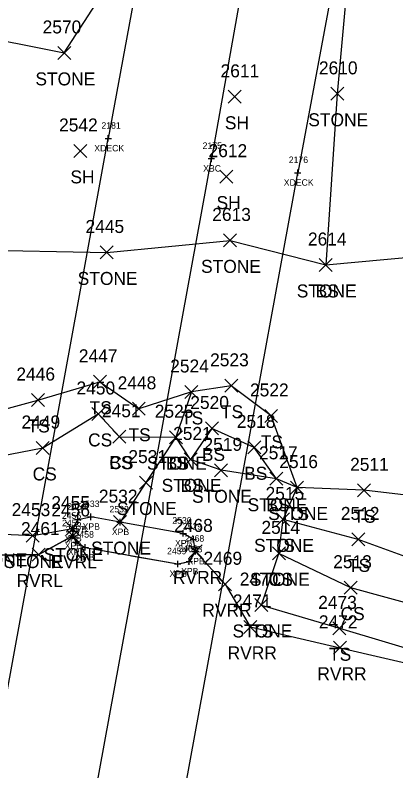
# Model space of a CAD drawing. Extents: x 1472022 to 1479249, y 777216 to 786527.
# Drawn here: x 1473693.9 to 1473752.5, y 779650.8 to 779767.2 of the extents above; entities that cross this region are included whole.
import ezdxf

# ---------------------------------------------------------------- set-up
doc = ezdxf.new("R2010")
doc.units = 0
for name, color, linetype in [('B_A', 7, 'Continuous'), ('B_I', 7, 'Continuous'), ('B_TIC', 7, 'Continuous'), ('BELB', 7, 'Continuous'), ('BSUBM', 7, 'Continuous'), ('L_A', 7, 'Continuous'), ('L_I', 7, 'Continuous'), ('L_TIC', 7, 'Continuous'), ('LASF', 7, 'Continuous'), ('LAWE', 7, 'Continuous'), ('LELB', 7, 'Continuous'), ('LSOGP', 7, 'Continuous')]:
    doc.layers.add(name, color=color, linetype=linetype)

msp = doc.modelspace()

# ---------------------------------------------------------------- linework, layer by layer
at = {"layer": 'B_TIC'}
for p, q in [((1473708.22, 779748.21), (1473708.3, 779748.21)), ((1473708.22, 779748.21), (1473708.3, 779748.21)), ((1473724.09, 779745.09), (1473724.17, 779745.09)), ((1473724.09, 779745.09), (1473724.17, 779745.09)), ((1473737.38, 779742.92), (1473737.46, 779742.92)), ((1473737.38, 779742.92), (1473737.46, 779742.92)), ((1473703.55, 779689.5), (1473703.62, 779689.5)), ((1473703.55, 779689.5), (1473703.62, 779689.5)), ((1473705.53, 779689.92), (1473705.6, 779689.92)), ((1473705.53, 779689.92), (1473705.6, 779689.92)), ((1473702.72, 779688.1), (1473702.79, 779688.1)), ((1473710.03, 779689.1), (1473710.1, 779689.1)), ((1473702.76, 779686.97), (1473702.84, 779686.97)), ((1473719.75, 779687.36), (1473719.82, 779687.36)), ((1473703.28, 779686.01), (1473703.36, 779686.01)), ((1473721.32, 779686.44), (1473721.39, 779686.44)), ((1473704.67, 779685.21), (1473704.74, 779685.21)), ((1473721.66, 779684.59), (1473721.74, 779684.59)), ((1473718.91, 779682.65), (1473718.98, 779682.65)), ((1473720.69, 779683.03), (1473720.76, 779683.03))]:
    msp.add_line(p, q, dxfattribs=at)
for points in [[(1473708.22, 779747.71), (1473708.22, 779748.71)], [(1473708.22, 779747.71), (1473708.22, 779748.71)], [(1473707.72, 779748.21), (1473708.72, 779748.21)], [(1473707.72, 779748.21), (1473708.72, 779748.21)], [(1473723.59, 779745.09), (1473724.59, 779745.09)], [(1473723.59, 779745.09), (1473724.59, 779745.09)], [(1473724.09, 779744.59), (1473724.09, 779745.59)], [(1473724.09, 779744.59), (1473724.09, 779745.59)], [(1473736.88, 779742.92), (1473737.88, 779742.92)], [(1473736.88, 779742.92), (1473737.88, 779742.92)], [(1473737.38, 779742.42), (1473737.38, 779743.42)], [(1473737.38, 779742.42), (1473737.38, 779743.42)], [(1473705.52, 779689.42), (1473705.52, 779690.42)], [(1473705.52, 779689.42), (1473705.52, 779690.42)], [(1473703.04, 779689.5), (1473704.04, 779689.5)], [(1473703.04, 779689.5), (1473704.04, 779689.5)], [(1473703.54, 779689), (1473703.54, 779690)], [(1473703.54, 779689), (1473703.54, 779690)], [(1473705.02, 779689.92), (1473706.02, 779689.92)], [(1473705.02, 779689.92), (1473706.02, 779689.92)], [(1473710.03, 779688.6), (1473710.03, 779689.6)], [(1473702.21, 779688.1), (1473703.21, 779688.1)], [(1473702.71, 779687.6), (1473702.71, 779688.6)], [(1473709.53, 779689.1), (1473710.53, 779689.1)], [(1473702.26, 779686.97), (1473703.26, 779686.97)], [(1473702.76, 779686.47), (1473702.76, 779687.47)], [(1473719.25, 779687.36), (1473720.25, 779687.36)], [(1473719.75, 779686.86), (1473719.75, 779687.86)], [(1473721.31, 779685.94), (1473721.31, 779686.94)], [(1473702.78, 779686.01), (1473703.78, 779686.01)], [(1473703.28, 779685.51), (1473703.28, 779686.51)], [(1473704.66, 779684.71), (1473704.66, 779685.71)], [(1473720.81, 779686.44), (1473721.81, 779686.44)], [(1473704.16, 779685.21), (1473705.16, 779685.21)], [(1473721.16, 779684.59), (1473722.16, 779684.59)], [(1473721.66, 779684.09), (1473721.66, 779685.09)], [(1473720.69, 779682.53), (1473720.69, 779683.53)], [(1473718.4, 779682.65), (1473719.4, 779682.65)], [(1473718.9, 779682.15), (1473718.9, 779683.15)], [(1473720.19, 779683.03), (1473721.19, 779683.03)]]:
    msp.add_lwpolyline(points, dxfattribs=at)
at = {"layer": 'BELB'}
for points in [[(1473719.43, 779809.21), (1473708.22, 779748.21)], [(1473735, 779806.45), (1473724.09, 779745.09)], [(1473748.73, 779803.86), (1473737.38, 779742.92)], [(1473632.64, 779331.64), (1473643.77, 779393.67), (1473661.77, 779492.35), (1473674.97, 779565.3), (1473690.2, 779649.78), (1473708.22, 779748.21)], [(1473648.23, 779328.95), (1473658.53, 779391.7), (1473677.73, 779489.35), (1473690.33, 779561.53), (1473706.17, 779646.87), (1473724.09, 779745.09)], [(1473662.07, 779326.37), (1473673.18, 779388.74), (1473691.04, 779487.09), (1473704.3, 779559.92), (1473719.46, 779644.73), (1473737.38, 779742.92)]]:
    msp.add_lwpolyline(points, dxfattribs=at)
at = {"layer": 'BSUBM'}
for points in [[(1473703.54, 779689.5), (1473702.71, 779688.1), (1473702.76, 779686.97), (1473703.28, 779686.01), (1473704.66, 779685.21), (1473718.9, 779682.65), (1473720.69, 779683.03), (1473721.66, 779684.59), (1473721.31, 779686.44), (1473719.75, 779687.36), (1473710.03, 779689.1), (1473705.52, 779689.92)], [(1473703.54, 779689.5), (1473705.52, 779689.92)]]:
    msp.add_lwpolyline(points, dxfattribs=at)
at = {"layer": 'L_TIC'}
for points in [[(1473700.45, 779760.38), (1473702.45, 779762.38)], [(1473702.45, 779760.38), (1473700.45, 779762.38)], [(1473726.67, 779753.62), (1473728.67, 779755.62)], [(1473728.67, 779753.62), (1473726.67, 779755.62)], [(1473742.47, 779754.08), (1473744.47, 779756.08)], [(1473744.47, 779754.08), (1473742.47, 779756.08)], [(1473702.9, 779745.28), (1473704.9, 779747.28)], [(1473704.9, 779745.28), (1473702.9, 779747.28)], [(1473725.39, 779741.32), (1473727.39, 779743.32)], [(1473727.39, 779741.32), (1473725.39, 779743.32)], [(1473725.96, 779731.5), (1473727.96, 779733.5)], [(1473727.96, 779731.5), (1473725.96, 779733.5)], [(1473706.97, 779729.64), (1473708.97, 779731.64)], [(1473708.97, 779729.64), (1473706.97, 779731.64)], [(1473740.69, 779727.71), (1473742.69, 779729.71)], [(1473742.69, 779727.71), (1473740.69, 779729.71)], [(1473740.69, 779727.71), (1473742.69, 779729.71)], [(1473742.69, 779727.71), (1473740.69, 779729.71)], [(1473740.69, 779727.71), (1473742.69, 779729.71)], [(1473742.69, 779727.71), (1473740.69, 779729.71)], [(1473705.94, 779709.72), (1473707.94, 779711.72)], [(1473707.94, 779709.72), (1473705.94, 779711.72)], [(1473720.01, 779708.15), (1473722.01, 779710.15)], [(1473722.01, 779708.15), (1473720.01, 779710.15)], [(1473726.15, 779709.1), (1473728.15, 779711.1)], [(1473728.15, 779709.1), (1473726.15, 779711.1)], [(1473696.38, 779706.91), (1473698.38, 779708.91)], [(1473698.38, 779706.91), (1473696.38, 779708.91)], [(1473705.67, 779704.76), (1473707.67, 779706.76)], [(1473707.67, 779704.76), (1473705.67, 779706.76)], [(1473711.92, 779705.56), (1473713.92, 779707.56)], [(1473713.92, 779705.56), (1473711.92, 779707.56)], [(1473732.29, 779704.46), (1473734.29, 779706.46)], [(1473734.29, 779704.46), (1473732.29, 779706.46)], [(1473723.18, 779702.53), (1473725.18, 779704.53)], [(1473725.18, 779702.53), (1473723.18, 779704.53)], [(1473708.93, 779701.26), (1473710.93, 779703.26)], [(1473710.93, 779701.26), (1473708.93, 779703.26)], [(1473708.93, 779701.26), (1473710.93, 779703.26)], [(1473710.93, 779701.26), (1473708.93, 779703.26)], [(1473717.63, 779701.18), (1473719.63, 779703.18)], [(1473719.63, 779701.18), (1473717.63, 779703.18)], [(1473717.63, 779701.18), (1473719.63, 779703.18)], [(1473719.63, 779701.18), (1473717.63, 779703.18)], [(1473717.63, 779701.18), (1473719.63, 779703.18)], [(1473719.63, 779701.18), (1473717.63, 779703.18)], [(1473697.13, 779699.52), (1473699.13, 779701.52)], [(1473699.13, 779699.52), (1473697.13, 779701.52)], [(1473729.69, 779699.62), (1473731.69, 779701.62)], [(1473731.69, 779699.62), (1473729.69, 779701.62)], [(1473719.89, 779697.76), (1473721.89, 779699.76)], [(1473721.89, 779697.76), (1473719.89, 779699.76)], [(1473719.89, 779697.76), (1473721.89, 779699.76)], [(1473721.89, 779697.76), (1473719.89, 779699.76)], [(1473724.57, 779696.08), (1473726.57, 779698.08)], [(1473726.57, 779696.08), (1473724.57, 779698.08)], [(1473713, 779694.19), (1473715, 779696.19)], [(1473715, 779694.19), (1473713, 779696.19)], [(1473733.11, 779694.77), (1473735.11, 779696.77)], [(1473735.11, 779694.77), (1473733.11, 779696.77)], [(1473733.11, 779694.77), (1473735.11, 779696.77)], [(1473735.11, 779694.77), (1473733.11, 779696.77)], [(1473736.29, 779693.42), (1473738.29, 779695.42)], [(1473738.29, 779693.42), (1473736.29, 779695.42)], [(1473736.29, 779693.42), (1473738.29, 779695.42)], [(1473738.29, 779693.42), (1473736.29, 779695.42)], [(1473746.56, 779693), (1473748.56, 779695)], [(1473748.56, 779693), (1473746.56, 779695)], [(1473734.12, 779688.52), (1473736.12, 779690.52)], [(1473736.12, 779688.52), (1473734.12, 779690.52)], [(1473734.12, 779688.52), (1473736.12, 779690.52)], [(1473736.12, 779688.52), (1473734.12, 779690.52)], [(1473709.03, 779688.1), (1473711.03, 779690.1)], [(1473711.03, 779688.1), (1473709.03, 779690.1)], [(1473695.6, 779686.02), (1473697.6, 779688.02)], [(1473697.6, 779686.02), (1473695.6, 779688.02)], [(1473701.71, 779687.1), (1473703.71, 779689.1)], [(1473703.71, 779687.1), (1473701.71, 779689.1)], [(1473701.76, 779685.97), (1473703.76, 779687.97)], [(1473703.76, 779685.97), (1473701.76, 779687.97)], [(1473745.7, 779685.44), (1473747.7, 779687.44)], [(1473747.7, 779685.44), (1473745.7, 779687.44)], [(1473696.52, 779683.1), (1473698.52, 779685.1)], [(1473698.52, 779683.1), (1473696.52, 779685.1)], [(1473720.66, 779683.59), (1473722.66, 779685.59)], [(1473722.66, 779683.59), (1473720.66, 779685.59)], [(1473733.48, 779683.29), (1473735.48, 779685.29)], [(1473735.48, 779683.29), (1473733.48, 779685.29)], [(1473733.48, 779683.29), (1473735.48, 779685.29)], [(1473735.48, 779683.29), (1473733.48, 779685.29)], [(1473725.19, 779678.53), (1473727.19, 779680.53)], [(1473727.19, 779678.53), (1473725.19, 779680.53)], [(1473744.53, 779678), (1473746.53, 779680)], [(1473746.53, 779678), (1473744.53, 779680)], [(1473730.8, 779675.33), (1473732.8, 779677.33)], [(1473732.8, 779675.33), (1473730.8, 779677.33)], [(1473730.8, 779675.33), (1473732.8, 779677.33)], [(1473732.8, 779675.33), (1473730.8, 779677.33)], [(1473729.08, 779671.96), (1473731.08, 779673.96)], [(1473731.08, 779671.96), (1473729.08, 779673.96)], [(1473742.79, 779671.74), (1473744.79, 779673.74)], [(1473744.79, 779671.74), (1473742.79, 779673.74)], [(1473742.89, 779668.74), (1473744.89, 779670.74)], [(1473744.89, 779668.74), (1473742.89, 779670.74)]]:
    msp.add_lwpolyline(points, dxfattribs=at)
at = {"layer": 'LASF'}
for points in [[(1473645.76, 779818.01), (1473644.27, 779813.32), (1473640.68, 779797.78), (1473635.77, 779778.37), (1473629.81, 779762.77), (1473624.6, 779746.95), (1473638.08, 779739.89), (1473662.02, 779736.43), (1473680.36, 779732.63), (1473687.24, 779731.02), (1473707.97, 779730.64), (1473726.96, 779732.5), (1473741.69, 779728.71)], [(1473674.63, 779812.66), (1473674.49, 779800.35), (1473673.09, 779784.2), (1473672.47, 779768.8), (1473686.21, 779764.41), (1473701.45, 779761.38), (1473708.8, 779772.85), (1473712.08, 779786.76), (1473716.54, 779806.01), (1473719.24, 779801.78), (1473727.32, 779798.69), (1473745.52, 779794.84), (1473745.88, 779788.84), (1473745.17, 779774.32), (1473743.47, 779755.08), (1473741.69, 779728.71)], [(1473556.2, 779785.03), (1473569.27, 779768.84), (1473581.85, 779759.61), (1473593.48, 779752.19), (1473598.64, 779740.18), (1473605.84, 779732.05), (1473622.09, 779716.93), (1473631.22, 779710.18), (1473652.96, 779708.5), (1473668.38, 779700.26), (1473681.15, 779692.51), (1473691, 779687.28), (1473696.6, 779687.02), (1473702.71, 779688.1)], [(1473731.8, 779676.33), (1473734.48, 779684.29), (1473735.12, 779689.52), (1473737.29, 779694.42), (1473734.11, 779695.77), (1473725.57, 779697.08), (1473720.89, 779698.76), (1473718.63, 779702.18), (1473714, 779695.19), (1473710.03, 779689.1)]]:
    msp.add_lwpolyline(points, dxfattribs=at)
at = {"layer": 'LAWE'}
for points in [[(1473702.76, 779686.97), (1473697.52, 779684.1), (1473689.85, 779684), (1473680.09, 779685.3), (1473668.84, 779689.31), (1473659.37, 779694.87), (1473652.17, 779699.65), (1473647.05, 779700.52)], [(1473721.66, 779684.59), (1473726.19, 779679.53), (1473730.08, 779672.96), (1473743.89, 779669.74), (1473756.99, 779666.69), (1473766.52, 779665.42), (1473779.36, 779661.55), (1473796.16, 779658.44), (1473812.33, 779658.77), (1473832.71, 779656.84), (1473845.94, 779659.73)]]:
    msp.add_lwpolyline(points, dxfattribs=at)
at = {"layer": 'LELB'}
for points in [[(1473604.95, 779751.89), (1473605.35, 779747.38), (1473618.12, 779740.94), (1473634.73, 779722.55), (1473655.83, 779716.43), (1473671, 779708.65), (1473684.35, 779704.32), (1473697.38, 779707.91), (1473706.94, 779710.72), (1473712.92, 779706.56)], [(1473605.35, 779747.38), (1473615.44, 779741.31), (1473625.67, 779718.9), (1473632.86, 779714.34), (1473652.96, 779708.5), (1473655.04, 779713.83), (1473670.13, 779704.35), (1473683.24, 779697.66), (1473698.13, 779700.52), (1473706.67, 779705.76), (1473709.93, 779702.26)], [(1473741.69, 779728.71), (1473760.69, 779730.5)], [(1473731.8, 779676.33), (1473743.79, 779672.74), (1473757.86, 779668.57), (1473767.48, 779668), (1473780.18, 779664.58), (1473797.83, 779661.81), (1473812.71, 779662.37), (1473833.32, 779661.88), (1473845.57, 779664.35), (1473842.75, 779671.88), (1473838.15, 779685.11), (1473839.47, 779701.41), (1473843.35, 779720.47)], [(1473786.63, 779699.66), (1473774.95, 779695.17), (1473765.42, 779691.9), (1473747.56, 779694), (1473737.29, 779694.42), (1473733.29, 779705.46), (1473727.15, 779710.1), (1473721.01, 779709.15), (1473718.63, 779702.18)], [(1473721.01, 779709.15), (1473712.92, 779706.56)], [(1473734.11, 779695.77), (1473730.69, 779700.62), (1473724.18, 779703.53), (1473720.89, 779698.76)], [(1473709.93, 779702.26), (1473718.63, 779702.18)], [(1473782.57, 779680.1), (1473773.11, 779680.16), (1473763.04, 779680.49), (1473746.7, 779686.44), (1473735.12, 779689.52)], [(1473783.07, 779678.55), (1473770.97, 779671.97), (1473762.43, 779674.36), (1473745.53, 779679), (1473734.48, 779684.29)]]:
    msp.add_lwpolyline(points, dxfattribs=at)
at = {"layer": 'LSOGP'}
msp.add_lwpolyline([(1473689.85, 779684), (1473697.52, 779684.1), (1473702.76, 779686.97), (1473703.28, 779686.01), (1473703.97, 779685.61), (1473704.66, 779685.21), (1473705.55, 779685.05), (1473706.44, 779684.89), (1473707.33, 779684.73), (1473708.22, 779684.57), (1473709.11, 779684.41), (1473710, 779684.25), (1473710.89, 779684.09), (1473711.78, 779683.93), (1473712.67, 779683.77), (1473713.56, 779683.61), (1473714.45, 779683.45), (1473715.34, 779683.29), (1473716.23, 779683.13), (1473717.12, 779682.97), (1473718.01, 779682.81), (1473718.9, 779682.65), (1473719.79, 779682.84), (1473720.69, 779683.03), (1473721.17, 779683.81), (1473721.66, 779684.59), (1473726.19, 779679.53), (1473730.08, 779672.96), (1473743.89, 779669.74), (1473756.99, 779666.69)], dxfattribs=at)

# ---------------------------------------------------------------- texts
at = {"layer": 'B_A'}
for s, p in [('XDECK', (1473706.06, 779746.21)), ('XDECK', (1473706.06, 779746.21)), ('XBC', (1473722.82, 779743.09)), ('XBC', (1473722.82, 779743.09)), ('XDECK', (1473735.22, 779740.92)), ('XDECK', (1473735.22, 779740.92)), ('XPB', (1473702.28, 779687.5)), ('XPB', (1473702.28, 779687.5)), ('XPB', (1473704.26, 779687.92)), ('XPB', (1473704.26, 779687.92)), ('XPB', (1473708.76, 779687.1)), ('XPB', (1473701.45, 779686.1)), ('XPB', (1473701.5, 779684.97)), ('XPB', (1473718.48, 779685.36)), ('XPB', (1473702.01, 779684.01)), ('XPB', (1473720.05, 779684.44)), ('XPB', (1473703.4, 779683.21)), ('XPB', (1473720.39, 779682.59)), ('XPB', (1473717.64, 779680.65)), ('XPB', (1473719.42, 779681.03))]:
    msp.add_text(s, height=1, dxfattribs=at).set_placement(p)
at = {"layer": 'B_I'}
for s, p in [('2181', (1473707.16, 779749.71)), ('2181', (1473707.16, 779749.71)), ('2175', (1473722.74, 779746.59)), ('2175', (1473722.74, 779746.59)), ('2176', (1473736, 779744.42)), ('2176', (1473736, 779744.42)), ('2454', (1473701.91, 779691)), ('2454', (1473701.91, 779691)), ('2533', (1473703.89, 779691.42)), ('2533', (1473703.89, 779691.42)), ('2532', (1473708.4, 779690.6)), ('2455', (1473701.08, 779689.6)), ('2456', (1473701.1, 779688.47)), ('2530', (1473718.07, 779688.86)), ('2457', (1473701.65, 779687.51)), ('2529', (1473719.68, 779687.94)), ('2458', (1473703.03, 779686.71)), ('2468', (1473720.01, 779686.09)), ('2459', (1473717.27, 779684.15)), ('2460', (1473718.99, 779684.53))]:
    msp.add_text(s, height=1, dxfattribs=at).set_placement(p)
at = {"layer": 'L_A'}
for s, p in [('STONE', (1473697, 779756.38)), ('STONE', (1473739.01, 779750.08)), ('SH', (1473726.16, 779749.62)), ('SH', (1473702.39, 779741.28)), ('SH', (1473724.88, 779737.32)), ('STONE', (1473722.5, 779727.5)), ('STONE', (1473703.51, 779725.64)), ('STONE', (1473737.23, 779723.71)), ('STONE', (1473737.23, 779723.71)), ('BS', (1473740.13, 779723.71)), ('TS', (1473705.34, 779705.72)), ('TS', (1473725.56, 779705.1)), ('TS', (1473719.42, 779704.15)), ('TS', (1473695.79, 779702.91)), ('TS', (1473711.33, 779701.56)), ('CS', (1473705.11, 779700.76)), ('TS', (1473731.7, 779700.46)), ('BS', (1473722.62, 779698.53)), ('CS', (1473708.37, 779697.26)), ('BS', (1473708.37, 779697.26)), ('STONE', (1473714.17, 779697.18)), ('TS', (1473717.03, 779697.18)), ('BS', (1473717.07, 779697.18)), ('CS', (1473696.57, 779695.52)), ('BS', (1473729.13, 779695.62)), ('STONE', (1473716.43, 779693.76)), ('BS', (1473719.33, 779693.76)), ('STONE', (1473721.11, 779692.08)), ('STONE', (1473729.66, 779690.77)), ('BS', (1473732.55, 779690.77)), ('STONE', (1473709.54, 779690.19)), ('STONE', (1473732.83, 779689.42)), ('TS', (1473735.7, 779689.42)), ('TS', (1473745.97, 779689)), ('STONE', (1473705.57, 779684.1)), ('STONE', (1473730.66, 779684.52)), ('TS', (1473733.53, 779684.52)), ('STONE', (1473698.26, 779683.1)), ('STONE', (1473686.54, 779682.28)), ('STONE', (1473692.14, 779682.02)), ('RVRL', (1473699.33, 779681.97)), ('TS', (1473745.11, 779681.44)), ('RVRL', (1473694.09, 779679.1)), ('RVRR', (1473718.17, 779679.59)), ('STONE', (1473730.02, 779679.29)), ('CS', (1473732.92, 779679.29)), ('RVRR', (1473722.7, 779674.53)), ('CS', (1473743.97, 779674)), ('STONE', (1473727.34, 779671.33)), ('TS', (1473730.21, 779671.33)), ('RVRR', (1473726.59, 779667.96)), ('TS', (1473742.2, 779667.74)), ('RVRR', (1473740.4, 779664.74))]:
    msp.add_text(s, height=2, dxfattribs=at).set_placement(p)
at = {"layer": 'L_I'}
for s, p in [('2570', (1473698.11, 779764.38)), ('2611', (1473725.5, 779757.62)), ('2610', (1473740.64, 779758.08)), ('2542', (1473700.64, 779749.28)), ('2612', (1473723.65, 779745.32)), ('2613', (1473724.22, 779735.5)), ('2445', (1473704.71, 779733.64)), ('2614', (1473738.95, 779731.71)), ('2614', (1473738.95, 779731.71)), ('2614', (1473738.95, 779731.71)), ('2447', (1473703.68, 779713.72)), ('2523', (1473723.89, 779713.1)), ('2524', (1473717.75, 779712.15)), ('2446', (1473694.07, 779710.91)), ('2448', (1473709.66, 779709.56)), ('2450', (1473703.32, 779708.76)), ('2522', (1473730.03, 779708.46)), ('2520', (1473720.84, 779706.53)), ('2451', (1473707.24, 779705.26)), ('2451', (1473707.24, 779705.26)), ('2525', (1473715.37, 779705.18)), ('2525', (1473715.37, 779705.18)), ('2525', (1473715.37, 779705.18)), ('2449', (1473694.86, 779703.52)), ('2518', (1473728, 779703.62)), ('2521', (1473718.2, 779701.76)), ('2521', (1473718.2, 779701.76)), ('2519', (1473722.87, 779700.08)), ('2517', (1473731.42, 779698.77)), ('2517', (1473731.42, 779698.77)), ('2531', (1473711.31, 779698.19)), ('2516', (1473734.54, 779697.42)), ('2516', (1473734.54, 779697.42)), ('2511', (1473745.44, 779697)), ('2532', (1473706.77, 779692.1)), ('2515', (1473732.43, 779692.52)), ('2515', (1473732.43, 779692.52)), ('2455', (1473699.45, 779691.1)), ('2453', (1473693.34, 779690.02)), ('2456', (1473699.45, 779689.97)), ('2512', (1473744.01, 779689.44)), ('2468', (1473718.35, 779687.59)), ('2514', (1473731.79, 779687.29)), ('2514', (1473731.79, 779687.29)), ('2461', (1473694.78, 779687.1)), ('2469', (1473722.87, 779682.53)), ('2513', (1473742.84, 779682)), ('2470', (1473728.45, 779679.33)), ('2470', (1473728.45, 779679.33)), ('2471', (1473727.39, 779675.96)), ('2473', (1473740.53, 779675.74)), ('2472', (1473740.63, 779672.74))]:
    msp.add_text(s, height=2, dxfattribs=at).set_placement(p)

doc.saveas('drawing.dxf')
